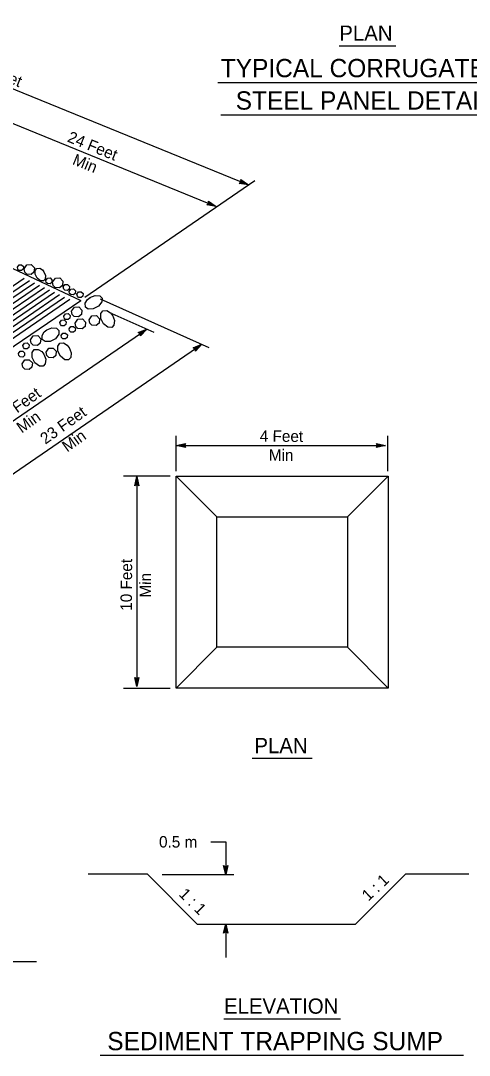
# Model space of a CAD drawing. Extents: x 6707406 to 6714471, y 1868570 to 1872341.
# Drawn here: x 6710038 to 6710320, y 1869785 to 1870437 of the extents above; entities that cross this region are included whole.
import ezdxf

# ---------------------------------------------------------------- set-up
doc = ezdxf.new("R2010")
doc.units = 0
for name, color, linetype in [('56 Stg 3 Anno', 7, 'Continuous'), ('57 Undefined', 7, 'Continuous'), ('60 Nongeo Data', 7, 'Continuous')]:
    doc.layers.add(name, color=color, linetype=linetype)

msp = doc.modelspace()

# ---------------------------------------------------------------- linework, layer by layer
at = {"layer": '56 Stg 3 Anno'}
for p, q in [((6709859.63, 1870464.61), (6710181.3, 1870333.54)), ((6710000.15, 1870385.54), (6710160.97, 1870320.01)), ((6710078.31, 1870262.74), (6710185.26, 1870336.25)), ((6710175.49, 1870334.53), (6710176.68, 1870335.42)), ((6710181.3, 1870333.54), (6710175.49, 1870334.53)), ((6710175.49, 1870334.53), (6710175.49, 1870334.53)), ((6710180.06, 1870334.04), (6710175.83, 1870334.76)), ((6710178.85, 1870334.54), (6710176.11, 1870335)), ((6710176.68, 1870335.42), (6710176.45, 1870336.9)), ((6710176.45, 1870336.9), (6710176.45, 1870336.9)), ((6710176.45, 1870336.9), (6710181.3, 1870333.54)), ((6710177.62, 1870335.04), (6710176.45, 1870335.24)), ((6710176.52, 1870336.51), (6710180.08, 1870334.04)), ((6710176.59, 1870336.1), (6710178.85, 1870334.54)), ((6710176.63, 1870335.73), (6710177.62, 1870335.04)), ((6710181.3, 1870333.54), (6710181.3, 1870333.54)), ((6710155.15, 1870321), (6710156.34, 1870321.89)), ((6710160.97, 1870320.01), (6710155.15, 1870321)), ((6710155.15, 1870321), (6710155.15, 1870321)), ((6710159.73, 1870320.51), (6710155.49, 1870321.24)), ((6710158.51, 1870321.01), (6710155.77, 1870321.48)), ((6710157.28, 1870321.51), (6710156.11, 1870321.71)), ((6710156.34, 1870321.89), (6710156.12, 1870323.38)), ((6710156.12, 1870323.38), (6710156.12, 1870323.38)), ((6710156.12, 1870323.38), (6710160.97, 1870320.01)), ((6710156.18, 1870322.98), (6710159.74, 1870320.51)), ((6710156.26, 1870322.58), (6710158.51, 1870321.01)), ((6710156.29, 1870322.2), (6710157.28, 1870321.51)), ((6710160.97, 1870320.01), (6710160.97, 1870320.01)), ((6710087.81, 1870261.86), (6710156.29, 1870231.14)), ((6710095.26, 1870252.59), (6710121.67, 1870240.75)), ((6709960.88, 1870135.33), (6710117.29, 1870242.71)), ((6710111.81, 1870240.51), (6710117.29, 1870242.71)), ((6710112.18, 1870240.35), (6710116.2, 1870241.96)), ((6710112.56, 1870240.19), (6710115.1, 1870241.21)), ((6710115.1, 1870241.21), (6710113.21, 1870239.18)), ((6710116.19, 1870241.95), (6710113.25, 1870238.81)), ((6710117.29, 1870242.71), (6710113.26, 1870238.4)), ((6710117.29, 1870242.71), (6710117.29, 1870242.71)), ((6710113.17, 1870239.89), (6710111.81, 1870240.51)), ((6710111.81, 1870240.51), (6710111.81, 1870240.51)), ((6710112.89, 1870240.01), (6710114.01, 1870240.46)), ((6710113.26, 1870238.4), (6710113.17, 1870239.89)), ((6710114.01, 1870240.46), (6710113.2, 1870239.59)), ((6710113.26, 1870238.4), (6710113.26, 1870238.4)), ((6709985.07, 1870118.55), (6710151.91, 1870233.1)), ((6710146.44, 1870230.9), (6710151.91, 1870233.1)), ((6710147.8, 1870230.28), (6710146.44, 1870230.9)), ((6710146.44, 1870230.9), (6710146.44, 1870230.9)), ((6710146.8, 1870230.74), (6710150.82, 1870232.35)), ((6710147.18, 1870230.58), (6710149.72, 1870231.6)), ((6710147.51, 1870230.4), (6710148.63, 1870230.85)), ((6710147.89, 1870228.79), (6710147.8, 1870230.28)), ((6710148.63, 1870230.85), (6710147.82, 1870229.98)), ((6710149.72, 1870231.6), (6710147.83, 1870229.57)), ((6710150.81, 1870232.34), (6710147.88, 1870229.2)), ((6710151.91, 1870233.1), (6710147.89, 1870228.79)), ((6710147.89, 1870228.79), (6710147.89, 1870228.79)), ((6710151.91, 1870233.1), (6710151.91, 1870233.1)), ((6710135.66, 1870175.49), (6710135.66, 1870153.14)), ((6710135.83, 1870169.28), (6710141.59, 1870170.56)), ((6710135.83, 1870169.28), (6710141.59, 1870170.56)), ((6710137.17, 1870169.28), (6710141.37, 1870170.21)), ((6710137.17, 1870169.28), (6710141.37, 1870170.21)), ((6710138.48, 1870169.28), (6710141.2, 1870169.88)), ((6710138.48, 1870169.28), (6710141.2, 1870169.88)), ((6710139.81, 1870169.28), (6710140.97, 1870169.54)), ((6710139.81, 1870169.28), (6710140.97, 1870169.54)), ((6710141.59, 1870170.56), (6710140.82, 1870169.28)), ((6710141.59, 1870170.56), (6710140.82, 1870169.28)), ((6710141.59, 1870170.56), (6710141.59, 1870170.56)), ((6710141.59, 1870170.56), (6710141.59, 1870170.56)), ((6710262.7, 1870169.28), (6710261.93, 1870170.57)), ((6710261.93, 1870170.57), (6710261.93, 1870170.57)), ((6710261.93, 1870170.57), (6710267.69, 1870169.28)), ((6710262.14, 1870170.23), (6710266.37, 1870169.28)), ((6710262.36, 1870169.88), (6710265.04, 1870169.28)), ((6710262.53, 1870169.55), (6710263.71, 1870169.28)), ((6710268.81, 1870175.49), (6710268.81, 1870153.14)), ((6710135.83, 1870169.28), (6710267.69, 1870169.28)), ((6710141.59, 1870168), (6710135.83, 1870169.28)), ((6710135.83, 1870169.28), (6710135.83, 1870169.28)), ((6710141.59, 1870168), (6710135.83, 1870169.28)), ((6710135.83, 1870169.28), (6710135.83, 1870169.28)), ((6710141.38, 1870168.34), (6710137.16, 1870169.28)), ((6710141.38, 1870168.34), (6710137.16, 1870169.28)), ((6710141.16, 1870168.68), (6710138.48, 1870169.28)), ((6710141.16, 1870168.68), (6710138.48, 1870169.28)), ((6710140.99, 1870169.02), (6710139.81, 1870169.28)), ((6710140.99, 1870169.02), (6710139.81, 1870169.28)), ((6710140.82, 1870169.28), (6710141.59, 1870168)), ((6710140.82, 1870169.28), (6710141.59, 1870168)), ((6710141.59, 1870168), (6710141.59, 1870168)), ((6710141.59, 1870168), (6710141.59, 1870168)), ((6710267.69, 1870169.28), (6710261.93, 1870168)), ((6710261.93, 1870168), (6710262.7, 1870169.28)), ((6710261.93, 1870168), (6710261.93, 1870168)), ((6710266.36, 1870169.28), (6710262.16, 1870168.35)), ((6710265.04, 1870169.28), (6710262.33, 1870168.68)), ((6710263.71, 1870169.28), (6710262.55, 1870169.03)), ((6710267.69, 1870169.28), (6710267.69, 1870169.28)), ((6710102.68, 1870150.28), (6710132.09, 1870150.28)), ((6710109.78, 1870144.02), (6710111.07, 1870149.78)), ((6710109.78, 1870144.02), (6710111.07, 1870149.78)), ((6710111.07, 1870144.79), (6710109.78, 1870144.02)), ((6710111.07, 1870144.79), (6710109.78, 1870144.02)), ((6710109.78, 1870144.02), (6710109.78, 1870144.02)), ((6710109.78, 1870144.02), (6710109.78, 1870144.02)), ((6710110.13, 1870144.23), (6710111.07, 1870148.45)), ((6710110.13, 1870144.23), (6710111.07, 1870148.45)), ((6710110.47, 1870144.45), (6710111.07, 1870147.13)), ((6710110.47, 1870144.45), (6710111.07, 1870147.13)), ((6710110.8, 1870144.62), (6710111.07, 1870145.8)), ((6710110.8, 1870144.62), (6710111.07, 1870145.8)), ((6710111.07, 1870149.78), (6710111.07, 1870017.51)), ((6710111.07, 1870149.78), (6710111.07, 1870149.78)), ((6710111.07, 1870149.78), (6710112.35, 1870144.02)), ((6710111.07, 1870149.78), (6710111.07, 1870149.78)), ((6710111.07, 1870149.78), (6710112.35, 1870144.02)), ((6710111.07, 1870148.44), (6710112, 1870144.24)), ((6710111.07, 1870148.44), (6710112, 1870144.24)), ((6710111.07, 1870147.13), (6710111.67, 1870144.41)), ((6710111.07, 1870147.13), (6710111.67, 1870144.41)), ((6710111.07, 1870145.8), (6710111.33, 1870144.64)), ((6710111.07, 1870145.8), (6710111.33, 1870144.64)), ((6710112.35, 1870144.02), (6710111.07, 1870144.79)), ((6710112.35, 1870144.02), (6710111.07, 1870144.79)), ((6710112.35, 1870144.02), (6710112.35, 1870144.02)), ((6710112.35, 1870144.02), (6710112.35, 1870144.02)), ((6710111.07, 1870017.51), (6710109.79, 1870023.27)), ((6710109.79, 1870023.27), (6710109.79, 1870023.27)), ((6710109.79, 1870023.27), (6710111.07, 1870022.51)), ((6710111.07, 1870018.85), (6710110.14, 1870023.05)), ((6710111.07, 1870020.17), (6710110.47, 1870022.88)), ((6710111.07, 1870021.49), (6710110.82, 1870022.65)), ((6710111.07, 1870022.51), (6710112.36, 1870023.27)), ((6710112.36, 1870023.27), (6710111.07, 1870017.51)), ((6710112.02, 1870023.07), (6710111.07, 1870018.84)), ((6710111.67, 1870022.84), (6710111.07, 1870020.17)), ((6710111.34, 1870022.67), (6710111.07, 1870021.49)), ((6710112.36, 1870023.27), (6710112.36, 1870023.27)), ((6710102.68, 1870016.4), (6710132.09, 1870016.4)), ((6710111.07, 1870017.51), (6710111.07, 1870017.51)), ((6710157.55, 1869919.67), (6710166.97, 1869919.67)), ((6710166.97, 1869919.67), (6710166.97, 1869898.98)), ((6710166.97, 1869898.98), (6710165.69, 1869904.74)), ((6710165.69, 1869904.74), (6710165.69, 1869904.74)), ((6710165.69, 1869904.74), (6710166.97, 1869903.97)), ((6710166.97, 1869900.31), (6710166.04, 1869904.51)), ((6710166.97, 1869901.63), (6710166.37, 1869904.34)), ((6710166.97, 1869902.95), (6710166.71, 1869904.11)), ((6710166.97, 1869903.97), (6710168.26, 1869904.74)), ((6710168.26, 1869904.74), (6710166.97, 1869898.98)), ((6710167.91, 1869904.53), (6710166.97, 1869900.3)), ((6710167.57, 1869904.3), (6710166.97, 1869901.63)), ((6710167.24, 1869904.13), (6710166.97, 1869902.95)), ((6710168.26, 1869904.74), (6710168.26, 1869904.74)), ((6710127.05, 1869898.98), (6710172.16, 1869898.98)), ((6710166.97, 1869898.98), (6710166.97, 1869898.98)), ((6710165.68, 1869862.07), (6710166.97, 1869867.83)), ((6710166.02, 1869862.27), (6710166.97, 1869866.5)), ((6710166.37, 1869862.5), (6710166.97, 1869865.17)), ((6710166.7, 1869862.67), (6710166.97, 1869863.85)), ((6710166.97, 1869867.83), (6710166.97, 1869846.68)), ((6710166.97, 1869867.83), (6710166.97, 1869867.83)), ((6710166.97, 1869867.83), (6710168.25, 1869862.07)), ((6710166.97, 1869866.49), (6710167.9, 1869862.29)), ((6710166.97, 1869865.17), (6710167.57, 1869862.46)), ((6710166.97, 1869863.85), (6710167.22, 1869862.69)), ((6710166.97, 1869862.83), (6710165.68, 1869862.07)), ((6710165.68, 1869862.07), (6710165.68, 1869862.07)), ((6710168.25, 1869862.07), (6710166.97, 1869862.83)), ((6710168.25, 1869862.07), (6710168.25, 1869862.07))]:
    msp.add_line(p, q, dxfattribs=at)
msp.add_lwpolyline([(6710040.02, 1870280.7), (6710041.76, 1870283.17), (6710044.53, 1870283.33), (6710046.46, 1870281.33), (6710046.18, 1870278.52), (6710044.47, 1870277.1), (6710041.73, 1870277.3), (6710040.44, 1870278.55), (6710040.02, 1870280.7)], dxfattribs=at)
at = {"layer": '57 Undefined'}
for p, q in [((6710238.45, 1870421.18), (6710274.16, 1870421.18)), ((6710161.92, 1870398.18), (6710350.68, 1870398.18)), ((6710163.84, 1870377.76), (6710347.49, 1870377.76)), ((6710183.63, 1869972.26), (6710221.5, 1869972.26)), ((6710165.85, 1869808.11), (6710239.28, 1869808.11)), ((6710087.83, 1869785.12), (6710316.74, 1869785.12))]:
    msp.add_line(p, q, dxfattribs=at)
at = {"layer": '60 Nongeo Data'}
for p, q in [((6710025.41, 1870284.39), (6710075.72, 1870260.77)), ((6709967.63, 1870225.48), (6710040.08, 1870274.86)), ((6709970.82, 1870223.99), (6710043.34, 1870273.42)), ((6709974, 1870222.49), (6710046.53, 1870271.93)), ((6709977.18, 1870221), (6710049.65, 1870270.4)), ((6709980.36, 1870219.51), (6710052.87, 1870268.93)), ((6709983.54, 1870218.01), (6710056.01, 1870267.4)), ((6709986.72, 1870216.52), (6710059.22, 1870265.93)), ((6709989.9, 1870215.03), (6710062.35, 1870264.41)), ((6709993.08, 1870213.53), (6710065.47, 1870262.87)), ((6709996.27, 1870212.04), (6710068.76, 1870261.45)), ((6709998.31, 1870208.01), (6710075.72, 1870260.77)), ((6710161.46, 1870124.39), (6710135.78, 1870150.07)), ((6710243.64, 1870124.39), (6710269.32, 1870150.07)), ((6710135.78, 1870016.54), (6710161.46, 1870042.22)), ((6710243.64, 1870042.22), (6710269.32, 1870016.54)), ((6710080.44, 1869899.37), (6710117.47, 1869899.37)), ((6710117.47, 1869899.37), (6710149, 1869867.83)), ((6710248.81, 1869867.83), (6710280.35, 1869899.37)), ((6710280.35, 1869899.37), (6710320.12, 1869899.37)), ((6710149, 1869867.83), (6710248.81, 1869867.83)), ((6709754.44, 1869844.14), (6710047.92, 1869844.14))]:
    msp.add_line(p, q, dxfattribs=at)
for points in [[(6710035.76, 1870281.7), (6710036.8, 1870283.19), (6710038.47, 1870283.28), (6710039.63, 1870282.08), (6710039.46, 1870280.4), (6710038.43, 1870279.54), (6710036.79, 1870279.66), (6710036.01, 1870280.41), (6710035.76, 1870281.7)], [(6710052.46, 1870278.84), (6710053.43, 1870276.4), (6710053.23, 1870274.16), (6710052.22, 1870273.09), (6710050.4, 1870273.12), (6710048.33, 1870274.74), (6710047.08, 1870277.24), (6710047.04, 1870279.6), (6710047.98, 1870280.92), (6710049.86, 1870281.05), (6710051.54, 1870279.97), (6710052.52, 1870278.74)], [(6710053.69, 1870273.4), (6710054.74, 1870274.88), (6710056.4, 1870274.97), (6710057.56, 1870273.77), (6710057.39, 1870272.09), (6710056.36, 1870271.24), (6710054.72, 1870271.35), (6710053.94, 1870272.1), (6710053.69, 1870273.4)], [(6710057.95, 1870272.28), (6710059.69, 1870274.76), (6710062.47, 1870274.91), (6710064.4, 1870272.91), (6710064.12, 1870270.11), (6710062.4, 1870268.68), (6710059.66, 1870268.88), (6710058.37, 1870270.13), (6710057.95, 1870272.28)], [(6710064.67, 1870269.24), (6710065.72, 1870270.72), (6710067.38, 1870270.82), (6710068.54, 1870269.61), (6710068.37, 1870267.93), (6710067.34, 1870267.08), (6710065.7, 1870267.19), (6710064.93, 1870267.95), (6710064.67, 1870269.24)], [(6710068.43, 1870266.44), (6710069.47, 1870267.92), (6710071.14, 1870268.02), (6710072.3, 1870266.82), (6710072.13, 1870265.13), (6710071.1, 1870264.28), (6710069.45, 1870264.4), (6710068.68, 1870265.15), (6710068.43, 1870266.44)], [(6710073.31, 1870264.69), (6710074.35, 1870266.17), (6710076.02, 1870266.27), (6710077.18, 1870265.07), (6710077.01, 1870263.38), (6710075.98, 1870262.53), (6710074.33, 1870262.65), (6710073.56, 1870263.4), (6710073.31, 1870264.69)], [(6710081.44, 1870262.56), (6710084.7, 1870263.85), (6710087.69, 1870263.59), (6710089.11, 1870262.24), (6710089.06, 1870259.82), (6710086.9, 1870257.06), (6710083.57, 1870255.4), (6710080.43, 1870255.34), (6710078.66, 1870256.6), (6710078.5, 1870259.1), (6710079.93, 1870261.33), (6710081.58, 1870262.65)], [(6710069.92, 1870254.03), (6710071.66, 1870256.51), (6710074.43, 1870256.66), (6710076.36, 1870254.66), (6710076.09, 1870251.86), (6710074.37, 1870250.43), (6710071.63, 1870250.63), (6710070.34, 1870251.88), (6710069.92, 1870254.03)], [(6710095.58, 1870251.43), (6710096.87, 1870248.18), (6710096.61, 1870245.19), (6710095.26, 1870243.77), (6710092.84, 1870243.81), (6710090.08, 1870245.97), (6710088.41, 1870249.3), (6710088.36, 1870252.44), (6710089.61, 1870254.21), (6710092.12, 1870254.37), (6710094.35, 1870252.94), (6710095.66, 1870251.3)], [(6710062.6, 1870246.87), (6710063.64, 1870248.35), (6710065.31, 1870248.45), (6710066.47, 1870247.25), (6710066.3, 1870245.57), (6710065.27, 1870244.71), (6710063.63, 1870244.83), (6710062.85, 1870245.58), (6710062.6, 1870246.87)], [(6710065.09, 1870250.86), (6710066.14, 1870252.34), (6710067.8, 1870252.44), (6710068.96, 1870251.24), (6710068.79, 1870249.55), (6710067.76, 1870248.7), (6710066.12, 1870248.82), (6710065.34, 1870249.57), (6710065.09, 1870250.86)], [(6710072.21, 1870246.46), (6710073.95, 1870248.93), (6710076.72, 1870249.09), (6710078.65, 1870247.09), (6710078.37, 1870244.28), (6710076.66, 1870242.86), (6710073.92, 1870243.05), (6710072.63, 1870244.31), (6710072.21, 1870246.46)], [(6710081.03, 1870248.55), (6710082.77, 1870251.02), (6710085.54, 1870251.18), (6710087.48, 1870249.18), (6710087.2, 1870246.37), (6710085.48, 1870244.95), (6710082.74, 1870245.15), (6710081.45, 1870246.4), (6710081.03, 1870248.55)], [(6710054.24, 1870242.15), (6710057.5, 1870243.44), (6710060.49, 1870243.18), (6710061.91, 1870241.83), (6710061.86, 1870239.4), (6710059.7, 1870236.65), (6710056.37, 1870234.98), (6710053.23, 1870234.93), (6710051.46, 1870236.18), (6710051.3, 1870238.68), (6710052.73, 1870240.92), (6710054.37, 1870242.23)], [(6710068.41, 1870242.84), (6710069.46, 1870244.32), (6710071.13, 1870244.41), (6710072.28, 1870243.21), (6710072.12, 1870241.53), (6710071.09, 1870240.68), (6710069.44, 1870240.79), (6710068.67, 1870241.54), (6710068.42, 1870242.84)], [(6710044.05, 1870235.93), (6710045.79, 1870238.41), (6710048.57, 1870238.57), (6710050.5, 1870236.57), (6710050.22, 1870233.76), (6710048.5, 1870232.33), (6710045.76, 1870232.53), (6710044.47, 1870233.78), (6710044.05, 1870235.93)], [(6710063.38, 1870238.63), (6710064.42, 1870240.11), (6710066.09, 1870240.21), (6710067.25, 1870239.01), (6710067.08, 1870237.32), (6710066.05, 1870236.47), (6710064.4, 1870236.59), (6710063.63, 1870237.34), (6710063.38, 1870238.63)], [(6710036.48, 1870227.27), (6710037.53, 1870228.76), (6710039.19, 1870228.85), (6710040.35, 1870227.65), (6710040.18, 1870225.97), (6710039.15, 1870225.11), (6710037.51, 1870225.23), (6710036.73, 1870225.98), (6710036.48, 1870227.27)], [(6710039.3, 1870232.38), (6710040.34, 1870233.87), (6710042.01, 1870233.96), (6710043.17, 1870232.76), (6710043, 1870231.08), (6710041.97, 1870230.22), (6710040.33, 1870230.34), (6710039.55, 1870231.09), (6710039.3, 1870232.38)], [(6710052.35, 1870226.96), (6710053.64, 1870223.71), (6710053.38, 1870220.72), (6710052.03, 1870219.3), (6710049.61, 1870219.34), (6710046.85, 1870221.5), (6710045.19, 1870224.83), (6710045.13, 1870227.97), (6710046.39, 1870229.74), (6710048.89, 1870229.91), (6710051.13, 1870228.48), (6710052.44, 1870226.83)], [(6710053.83, 1870228.13), (6710055.57, 1870230.61), (6710058.34, 1870230.77), (6710060.27, 1870228.76), (6710060, 1870225.96), (6710058.28, 1870224.53), (6710055.54, 1870224.73), (6710054.25, 1870225.98), (6710053.83, 1870228.13)], [(6710068.38, 1870231.02), (6710069.67, 1870227.76), (6710069.41, 1870224.77), (6710068.06, 1870223.35), (6710065.64, 1870223.4), (6710062.88, 1870225.55), (6710061.21, 1870228.89), (6710061.16, 1870232.03), (6710062.41, 1870233.79), (6710064.92, 1870233.96), (6710067.15, 1870232.53), (6710068.46, 1870230.88)], [(6710038.77, 1870220.78), (6710040.51, 1870223.26), (6710043.28, 1870223.42), (6710045.22, 1870221.41), (6710044.94, 1870218.61), (6710043.22, 1870217.18), (6710040.48, 1870217.38), (6710039.19, 1870218.63), (6710038.77, 1870220.78)]]:
    msp.add_lwpolyline(points, dxfattribs=at)
for points in [[(6710269.32, 1870016.54), (6710135.78, 1870016.54), (6710135.78, 1870150.07), (6710269.32, 1870150.07)], [(6710243.64, 1870042.22), (6710161.46, 1870042.22), (6710161.46, 1870124.39), (6710243.64, 1870124.39)]]:
    msp.add_lwpolyline(points, close=True, dxfattribs=at)

# ---------------------------------------------------------------- texts
at = {"layer": '57 Undefined'}
for s, height, p in [('PLAN', 9.6, (6710238.51, 1870424.39)), ('TYPICAL CORRUGATED', 11.5203, (6710163.9, 1870401.4)), ('STEEL PANEL DETAIL', 11.5203, (6710173.28, 1870380.98)), ('PLAN', 9.6, (6710185.03, 1869975.48)), ('ELEVATION', 9.6, (6710165.89, 1869811.33)), ('SEDIMENT TRAPPING SUMP', 11.5203, (6710092.38, 1869788.33))]:
    msp.add_text(s, height=height, dxfattribs=at).set_placement(p)
for s, rotation, p in [('50 Feet', 337.82938, (6710006.64, 1870407.3)), ('24 Feet', 337.82938, (6710066.73, 1870361)), ('Min', 337.82938, (6710069.93, 1870346.74)), ('20 Feet', 35.46566, (6710024.73, 1870181.74)), ('Min', 35.46566, (6710038.5, 1870176.81)), ('23 Feet', 35.46566, (6710053.39, 1870169.8)), ('Min', 35.46566, (6710067.16, 1870164.87)), ('4 Feet', 359.6363, (6710188.44, 1870171.76)), ('Min', 359.6363, (6710194.1, 1870159.73)), ('10 Feet', 89.6363, (6710107.87, 1870065.22)), ('Min', 89.6363, (6710119.92, 1870073.5)), ('0.5 m', 359.6363, (6710124.97, 1869916.07)), ('1 : 1', 43.25519, (6710256.82, 1869881.9)), ('1 : 1', 315.66558, (6710136.99, 1869886.07))]:
    msp.add_text(s, height=7.2, rotation=rotation, dxfattribs=at).set_placement(p)

doc.saveas('drawing.dxf')
